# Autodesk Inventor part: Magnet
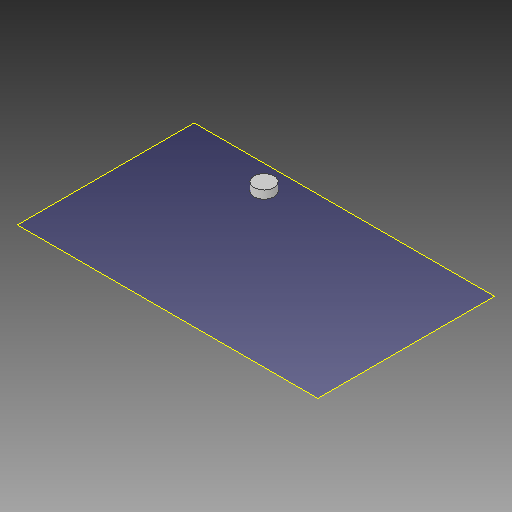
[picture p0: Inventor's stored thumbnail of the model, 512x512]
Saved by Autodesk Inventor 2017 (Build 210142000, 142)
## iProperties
Created: 2017-05
Part Number: Magnet
Material: Generic
Document SubType Name: Modeling
Designer: Savy
Density: 1 g/cm^3
Appearance: Default
Mass: 0.159593 g
Surface Area: 1.80327 cm^2
Volume: 0.159593 cm^3
Author: Savy
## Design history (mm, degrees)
workplane "Work Plane1"
sketch "Sketch1"
  geometry: C1 r 4 at (-22.225, 25.4) reference; C2 r 4 at (-22.225, 25.4); 1 further point
  constraints: 1 centre point, 1 coincident, 1 concentric
extrude "Extrusion1" new body sketch "Sketch1" distance "d0" = 3.175; taper "d1" = 0 deg
body "Solid1"
node "Reference1"
